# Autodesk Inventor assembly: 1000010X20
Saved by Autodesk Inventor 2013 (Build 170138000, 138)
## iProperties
Company: TraceParts S.A.
Created: 2015-09
Part Number: 1000010X20
Checked By: TraceParts S.A.
Catalog Web Link: www.traceparts.com
Vendor: Emile Maurin
Document SubType Name: Assembly
Designer: TraceParts
REFERENCE: 1000010X20
SUPPLIER: Emile Maurin
TraceParts.PartNumber: 10-22122011-066269
TraceParts.PartTitle: 10000 : BOULON A TETE HEXAGONALE ISO 4014 - 4017 / 4032 ACIER CLASSE 6.8 - BRUT
TraceParts.InstanceId: 10-22122011-066269209PMXP1EX2OGCU7CC0IH9YXF
TraceParts.PartStatus: Published
TraceParts.PartVersion: 1.0.5
TRACEPARTS: TRACEPARTS
TraceParts.PartLanguage: fr
TraceParts.ClassPath: EMILE_MAURIN_BV:/EM_BV/BV/GRP_A_b_1/FOR_A1_b_2/10-22122011-066269
Author: TraceParts
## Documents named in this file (3)
- J:\SAUVEGARDE 2013 Juillet\OL1 (U)\TRAVAUX\2014-2015\u11 sujet bac\Modele Grue rotative\Boulon H M10x20.iam
- J:\SAUVEGARDE 2013 Juillet\OL1 (U)\TRAVAUX\2014-2015\u11 sujet bac\Modele Grue rotative\Vis H M10x20_02.ipt
- J:\SAUVEGARDE 2013 Juillet\OL1 (U)\TRAVAUX\2014-2015\u11 sujet bac\Modele Grue rotative\Ecrou H M10x20_01.ipt
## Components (2 placed, 2 different names)
1. Vis H M10x20_02:1
2. Ecrou H M10x20_01:1
